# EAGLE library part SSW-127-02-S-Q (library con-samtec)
THROUGH-HOLE .025" SQ POST SOCKET Source: Samtec SSW.pdf
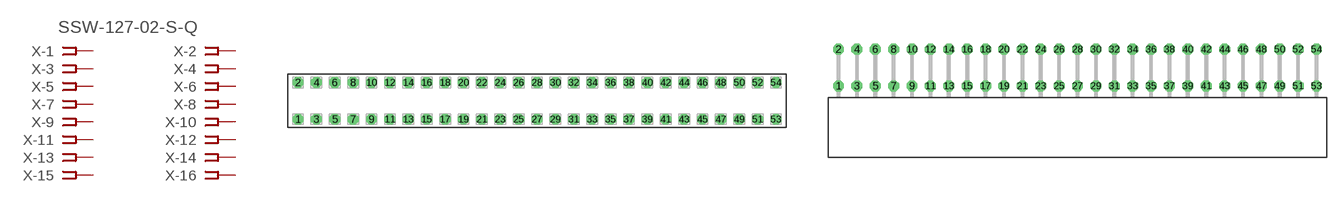
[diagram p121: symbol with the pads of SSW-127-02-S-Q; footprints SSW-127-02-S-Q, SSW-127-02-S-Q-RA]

Designator prefix X; gates -1=FPINV -2=FPIN -3=FPIN -4=FPIN -5=FPIN -6=FPIN -7=FPIN -8=FPIN -9=FPIN -10=FPIN -11=FPIN -12=FPIN -13=FPIN -14=FPIN -15=FPIN -16=FPIN -17=FPIN -18=FPIN -19=FPIN -20=FPIN -21=FPIN -22=FPIN -23=FPIN -24=FPIN -25=FPIN -26=FPIN -27=FPIN -28=FPIN -29=FPIN -30=FPIN -31=FPIN -32=FPIN -33=FPIN -34=FPIN -35=FPIN -36=FPIN -37=FPIN -38=FPIN -39=FPIN -40=FPIN -41=FPIN -42=FPIN -43=FPIN -44=FPIN -45=FPIN -46=FPIN -47=FPIN -48=FPIN -49=FPIN -50=FPIN -51=FPIN -52=FPIN -53=FPIN -54=FPIN

## SSW-127-02-S-Q (MPN: SSW-127-02-S-Q; OC_FARNELL: unknown; OC_NEWARK: 82P9693)  [SSW-127-02-S-Q]
1  -1:1  pas
2  -2:1  pas
3  -3:1  pas
4  -4:1  pas
5  -5:1  pas
6  -6:1  pas
7  -7:1  pas
8  -8:1  pas
9  -9:1  pas
10  -10:1  pas
11  -11:1  pas
12  -12:1  pas
13  -13:1  pas
14  -14:1  pas
15  -15:1  pas
16  -16:1  pas
17  -17:1  pas
18  -18:1  pas
19  -19:1  pas
20  -20:1  pas
21  -21:1  pas
22  -22:1  pas
23  -23:1  pas
24  -24:1  pas
25  -25:1  pas
26  -26:1  pas
27  -27:1  pas
28  -28:1  pas
29  -29:1  pas
30  -30:1  pas
31  -31:1  pas
32  -32:1  pas
33  -33:1  pas
34  -34:1  pas
35  -35:1  pas
36  -36:1  pas
37  -37:1  pas
38  -38:1  pas
39  -39:1  pas
40  -40:1  pas
41  -41:1  pas
42  -42:1  pas
43  -43:1  pas
44  -44:1  pas
45  -45:1  pas
46  -46:1  pas
47  -47:1  pas
48  -48:1  pas
49  -49:1  pas
50  -50:1  pas
51  -51:1  pas
52  -52:1  pas
53  -53:1  pas
54  -54:1  pas

## SSW-127-02-S-QRA (MPN: SSW-127-02-S-Q-RA; OC_FARNELL: unknown; OC_NEWARK: 82P9694)  [SSW-127-02-S-Q-RA]
Pads as for SSW-127-02-S-Q

## Footprint SSW-127-02-S-Q (pad centres in mm)
THROUGH-HOLE .025" SQ POST SOCKET Source: Samtec SSW.pdf
drill 1 pad 1.5 octagon: 1 -33.02,-2.54; 2 -33.02,2.54; 3 -30.48,-2.54; 4 -30.48,2.54; 5 -27.94,-2.54; 6 -27.94,2.54; 7 -25.4,-2.54; 8 -25.4,2.54; 9 -22.86,-2.54; 10 -22.86,2.54; 11 -20.32,-2.54; 12 -20.32,2.54; 13 -17.78,-2.54; 14 -17.78,2.54; 15 -15.24,-2.54; 16 -15.24,2.54; 17 -12.7,-2.54; 18 -12.7,2.54; 19 -10.16,-2.54; 20 -10.16,2.54; 21 -7.62,-2.54; 22 -7.62,2.54; 23 -5.08,-2.54; 24 -5.08,2.54; 25 -2.54,-2.54; 26 -2.54,2.54; 27 0,-2.54; 28 0,2.54; 29 2.54,-2.54; 30 2.54,2.54; 31 5.08,-2.54; 32 5.08,2.54; 33 7.62,-2.54; 34 7.62,2.54; 35 10.16,-2.54; 36 10.16,2.54; 37 12.7,-2.54; 38 12.7,2.54; 39 15.24,-2.54; 40 15.24,2.54; 41 17.78,-2.54; 42 17.78,2.54; 43 20.32,-2.54; 44 20.32,2.54; 45 22.86,-2.54; 46 22.86,2.54; 47 25.4,-2.54; 48 25.4,2.54; 49 27.94,-2.54; 50 27.94,2.54; 51 30.48,-2.54; 52 30.48,2.54; 53 33.02,-2.54; 54 33.02,2.54

## Footprint SSW-127-02-S-Q-RA (pad centres in mm)
THROUGH-HOLE .025" SQ POST SOCKET Source: Samtec SSW.pdf
drill 1 pad 1.5 octagon: 1 -33.02,1.524; 2 -33.02,6.604; 3 -30.48,1.524; 4 -30.48,6.604; 5 -27.94,1.524; 6 -27.94,6.604; 7 -25.4,1.524; 8 -25.4,6.604; 9 -22.86,1.524; 10 -22.86,6.604; 11 -20.32,1.524; 12 -20.32,6.604; 13 -17.78,1.524; 14 -17.78,6.604; 15 -15.24,1.524; 16 -15.24,6.604; 17 -12.7,1.524; 18 -12.7,6.604; 19 -10.16,1.524; 20 -10.16,6.604; 21 -7.62,1.524; 22 -7.62,6.604; 23 -5.08,1.524; 24 -5.08,6.604; 25 -2.54,1.524; 26 -2.54,6.604; 27 0,1.524; 28 0,6.604; 29 2.54,1.524; 30 2.54,6.604; 31 5.08,1.524; 32 5.08,6.604; 33 7.62,1.524; 34 7.62,6.604; 35 10.16,1.524; 36 10.16,6.604; 37 12.7,1.524; 38 12.7,6.604; 39 15.24,1.524; 40 15.24,6.604; 41 17.78,1.524; 42 17.78,6.604; 43 20.32,1.524; 44 20.32,6.604; 45 22.86,1.524; 46 22.86,6.604; 47 25.4,1.524; 48 25.4,6.604; 49 27.94,1.524; 50 27.94,6.604; 51 30.48,1.524; 52 30.48,6.604; 53 33.02,1.524; 54 33.02,6.604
